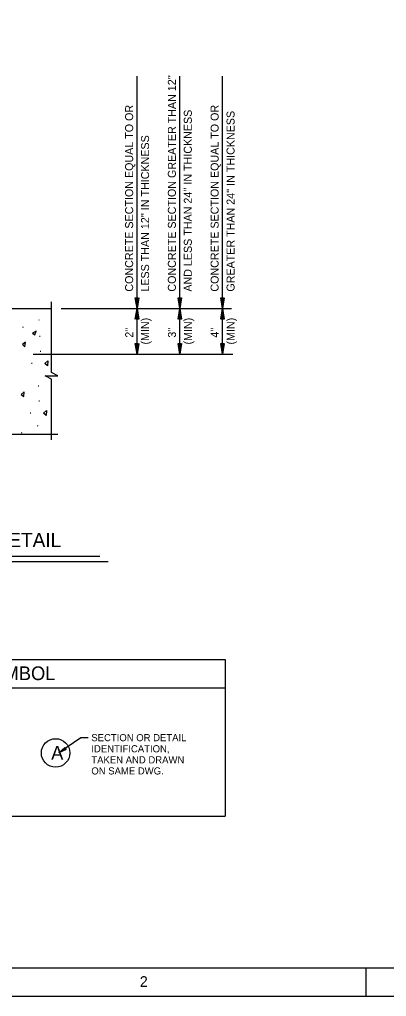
# Model space of a CAD drawing. Extents: x 22369.62 to 22373.29, y 22369.62 to 22372.46.
# Drawn here: x 22370.546 to 22371.083, y 22369.621 to 22371.049 of the extents above; entities that cross this region are included whole.
import ezdxf

# ---------------------------------------------------------------- set-up
doc = ezdxf.new("R2010")
doc.units = 0
for name, color, linetype in [('Default', 7, 'Continuous'), ('Level 1', 7, 'Continuous'), ('Level 10', 7, 'Continuous'), ('Level 2', 7, 'Continuous'), ('Level 3', 7, 'Continuous'), ('Level 4', 7, 'Continuous'), ('Level 8', 7, 'Continuous'), ('Level 9', 7, 'Continuous')]:
    doc.layers.add(name, color=color, linetype=linetype)

msp = doc.modelspace()

# ---------------------------------------------------------------- linework, layer by layer
at = {"layer": 'Default'}
for p, q in [((22370.575, 22370.6094), (22370.5741, 22370.6096)), ((22370.5514, 22370.5996), (22370.5504, 22370.5991)), ((22370.5763, 22370.5858), (22370.5752, 22370.5858)), ((22370.5772, 22370.5639), (22370.5761, 22370.5636)), ((22370.5644, 22370.5465), (22370.5635, 22370.5464)), ((22370.5745, 22370.5132), (22370.5734, 22370.5132)), ((22370.5929, 22370.5136), (22370.5921, 22370.5136)), ((22370.5754, 22370.4914), (22370.5743, 22370.4911)), ((22370.5626, 22370.4739), (22370.5617, 22370.4738)), ((22370.5496, 22370.445), (22370.5486, 22370.4445)), ((22370.5732, 22370.4549), (22370.5723, 22370.455))]:
    msp.add_line(p, q, dxfattribs=at)
for points in [[(22370.5684, 22370.5882), (22370.5704, 22370.5933), (22370.5649, 22370.5906)], [(22370.5548, 22370.5775), (22370.5505, 22370.5738), (22370.554, 22370.5708)], [(22370.587, 22370.5428), (22370.5831, 22370.5464), (22370.5874, 22370.5502)], [(22370.553, 22370.5049), (22370.5487, 22370.5012), (22370.5522, 22370.4982)], [(22370.5852, 22370.4702), (22370.5813, 22370.4738), (22370.5856, 22370.4776)]]:
    msp.add_lwpolyline(points, close=True, dxfattribs=at)
at = {"layer": 'Level 1'}
for p, q in [((22370.7179, 22370.6266), (22370.7179, 22370.9663)), ((22370.7804, 22370.6266), (22370.7804, 22370.9663)), ((22370.8429, 22370.6266), (22370.8429, 22370.9663)), ((22370.8429, 22370.6266), (22370.8429, 22370.7116)), ((22370.5929, 22370.533), (22370.5929, 22370.6363)), ((22370.607, 22370.6266), (22370.8559, 22370.6266)), ((22370.7179, 22370.5599), (22370.7179, 22370.6266)), ((22370.7804, 22370.5599), (22370.7804, 22370.6266)), ((22370.8429, 22370.5599), (22370.8429, 22370.6266)), ((22370.5659, 22370.5599), (22370.8582, 22370.5599)), ((22370.6022, 22370.5283), (22370.5929, 22370.533)), ((22370.5929, 22370.5236), (22370.5835, 22370.5283)), ((22370.5835, 22370.5283), (22370.6022, 22370.5283)), ((22370.5929, 22370.4349), (22370.5929, 22370.5236)), ((22370.3594, 22370.4432), (22370.6021, 22370.4432)), ((22370.6036, 22369.9771), (22370.6036, 22369.9771)), ((22370.6062, 22369.979), (22370.6062, 22369.979))]:
    msp.add_line(p, q, dxfattribs=at)
msp.add_lwpolyline([(22369.6213, 22372.4553), (22373.288, 22372.4553), (22373.288, 22369.6213), (22369.6213, 22369.6213)], close=True, dxfattribs=at)
for points in [[(22370.6465, 22369.9992), (22370.6356, 22369.9992), (22370.6036, 22369.9771)], [(22370.6143, 22369.9821), (22370.6036, 22369.9771), (22370.6121, 22369.9853), (22370.614, 22369.9826), (22370.6062, 22369.979), (22370.612, 22369.9845), (22370.6132, 22369.9828), (22370.6088, 22369.9807), (22370.612, 22369.9837), (22370.6125, 22369.983), (22370.6115, 22369.9826)]]:
    msp.add_lwpolyline(points, dxfattribs=at)
at = {"layer": 'Level 10'}
for p, q in [((22370.1262, 22370.6266), (22370.5929, 22370.6266)), ((22370.066, 22370.2646), (22370.6636, 22370.2646)), ((22370.0558, 22370.2568), (22370.6756, 22370.2568)), ((22370.0135, 22370.1138), (22370.8468, 22370.1138)), ((22370.8468, 22370.1138), (22370.8468, 22369.8847)), ((22370.0135, 22370.0722), (22370.8468, 22370.0722)), ((22370.0135, 22369.8847), (22370.8468, 22369.8847)), ((22371.053, 22369.6213), (22371.053, 22369.6633))]:
    msp.add_line(p, q, dxfattribs=at)
at = {"layer": 'Level 2'}
for points in [[(22370.7205, 22370.6421), (22370.7179, 22370.6266), (22370.7153, 22370.6421), (22370.7197, 22370.6421), (22370.7179, 22370.6309), (22370.7161, 22370.6415), (22370.719, 22370.6415), (22370.7179, 22370.6351), (22370.717, 22370.6408), (22370.7181, 22370.6408), (22370.7179, 22370.6394)], [(22370.783, 22370.6421), (22370.7804, 22370.6266), (22370.7778, 22370.6421), (22370.7822, 22370.6421), (22370.7804, 22370.6309), (22370.7786, 22370.6415), (22370.7815, 22370.6415), (22370.7804, 22370.6351), (22370.7795, 22370.6408), (22370.7806, 22370.6408), (22370.7804, 22370.6394)], [(22370.8455, 22370.6421), (22370.8429, 22370.6266), (22370.8403, 22370.6421), (22370.8447, 22370.6421), (22370.8429, 22370.6309), (22370.8411, 22370.6415), (22370.844, 22370.6415), (22370.8429, 22370.6351), (22370.842, 22370.6408), (22370.8431, 22370.6408), (22370.8429, 22370.6394)], [(22370.7153, 22370.611), (22370.7179, 22370.6266), (22370.7205, 22370.611), (22370.716, 22370.611), (22370.7179, 22370.6222), (22370.7196, 22370.6116), (22370.7168, 22370.6116), (22370.7179, 22370.6181), (22370.7188, 22370.6123), (22370.7176, 22370.6123), (22370.7179, 22370.6137)], [(22370.7778, 22370.611), (22370.7804, 22370.6266), (22370.783, 22370.611), (22370.7785, 22370.611), (22370.7804, 22370.6222), (22370.7821, 22370.6116), (22370.7793, 22370.6116), (22370.7804, 22370.6181), (22370.7813, 22370.6123), (22370.7801, 22370.6123), (22370.7804, 22370.6137)], [(22370.8403, 22370.611), (22370.8429, 22370.6266), (22370.8455, 22370.611), (22370.841, 22370.611), (22370.8429, 22370.6222), (22370.8446, 22370.6116), (22370.8418, 22370.6116), (22370.8429, 22370.6181), (22370.8438, 22370.6123), (22370.8426, 22370.6123), (22370.8429, 22370.6137)], [(22370.7205, 22370.5755), (22370.7179, 22370.5599), (22370.7153, 22370.5755), (22370.7197, 22370.5755), (22370.7179, 22370.5642), (22370.7161, 22370.5748), (22370.719, 22370.5748), (22370.7179, 22370.5684), (22370.717, 22370.5741), (22370.7181, 22370.5741), (22370.7179, 22370.5727)], [(22370.783, 22370.5755), (22370.7804, 22370.5599), (22370.7778, 22370.5755), (22370.7822, 22370.5755), (22370.7804, 22370.5642), (22370.7786, 22370.5748), (22370.7815, 22370.5748), (22370.7804, 22370.5684), (22370.7795, 22370.5741), (22370.7806, 22370.5741), (22370.7804, 22370.5727)], [(22370.8455, 22370.5755), (22370.8429, 22370.5599), (22370.8403, 22370.5755), (22370.8447, 22370.5755), (22370.8429, 22370.5642), (22370.8411, 22370.5748), (22370.844, 22370.5748), (22370.8429, 22370.5684), (22370.842, 22370.5741), (22370.8431, 22370.5741), (22370.8429, 22370.5727)]]:
    msp.add_lwpolyline(points, dxfattribs=at)
at = {"layer": 'Level 3'}
msp.add_circle((22370.5988, 22369.9772), 0.0208, dxfattribs=at)
at = {"layer": 'Level 8'}
for p, q in [((22370.7179, 22370.6309), (22370.7179, 22370.6309)), ((22370.7804, 22370.6309), (22370.7804, 22370.6309)), ((22370.8429, 22370.6309), (22370.8429, 22370.6309)), ((22370.7179, 22370.6266), (22370.7179, 22370.6266)), ((22370.7179, 22370.6266), (22370.7179, 22370.6266)), ((22370.7179, 22370.6222), (22370.7179, 22370.6222)), ((22370.7804, 22370.6266), (22370.7804, 22370.6266)), ((22370.7804, 22370.6266), (22370.7804, 22370.6266)), ((22370.7804, 22370.6222), (22370.7804, 22370.6222)), ((22370.8429, 22370.6266), (22370.8429, 22370.6266)), ((22370.8429, 22370.6266), (22370.8429, 22370.6266)), ((22370.8429, 22370.6222), (22370.8429, 22370.6222)), ((22370.7179, 22370.5642), (22370.7179, 22370.5642)), ((22370.7179, 22370.5599), (22370.7179, 22370.5599)), ((22370.7804, 22370.5642), (22370.7804, 22370.5642)), ((22370.7804, 22370.5599), (22370.7804, 22370.5599)), ((22370.8429, 22370.5642), (22370.8429, 22370.5642)), ((22370.8429, 22370.5599), (22370.8429, 22370.5599))]:
    msp.add_line(p, q, dxfattribs=at)
at = {"layer": 'Level 9'}
msp.add_line((22369.7463, 22369.6633), (22373.017, 22369.6633), dxfattribs=at)

# ---------------------------------------------------------------- texts
at = {"layer": 'Level 1'}
msp.add_text('2', height=0.0156, dxfattribs=at).set_placement((22370.722, 22369.6353))
at = {"layer": 'Level 3'}
for s, height, p in [('REINFORCEMENT CLEARANCE DETAIL', 0.020802, (22370.0815, 22370.278)), ('SECTION OR DETAIL SYMBOL', 0.02, (22370.2122, 22370.0836)), ('A', 0.02, (22370.5923, 22369.9672))]:
    msp.add_text(s, height=height, dxfattribs=at).set_placement(p)
at = {"layer": 'Level 4'}
for s, height, p in [("CONCRETE SECTION GREATER THAN 12''", 0.011698, (22370.7747, 22370.6513)), ('CONCRETE SECTION EQUAL TO OR', 0.011698, (22370.7122, 22370.6513)), ("AND LESS THAN 24'' IN THICKNESS", 0.011698, (22370.798, 22370.6513)), ('CONCRETE SECTION EQUAL TO OR', 0.011698, (22370.8372, 22370.6513)), ("GREATER THAN 24'' IN THICKNESS", 0.011698, (22370.8605, 22370.6513)), ("LESS THAN 12'' IN THICKNESS", 0.011698, (22370.7355, 22370.6513)), ('(MIN)', 0.0117, (22370.7356, 22370.574)), ('(MIN)', 0.0117, (22370.7981, 22370.574)), ('(MIN)', 0.0117, (22370.8606, 22370.574)), ("2''", 0.0117, (22370.7123, 22370.584)), ("3''", 0.0117, (22370.7748, 22370.584)), ("4''", 0.0117, (22370.8373, 22370.584))]:
    msp.add_text(s, height=height, rotation=90, dxfattribs=at).set_placement(p)
for s, p in [('SECTION OR DETAIL', (22370.6511, 22369.9943)), ('IDENTIFICATION,', (22370.6511, 22369.9781)), ('TAKEN AND DRAWN', (22370.6511, 22369.9619)), ('ON SAME DWG.', (22370.6511, 22369.9457))]:
    msp.add_text(s, height=0.010396, dxfattribs=at).set_placement(p)

doc.saveas('drawing.dxf')
